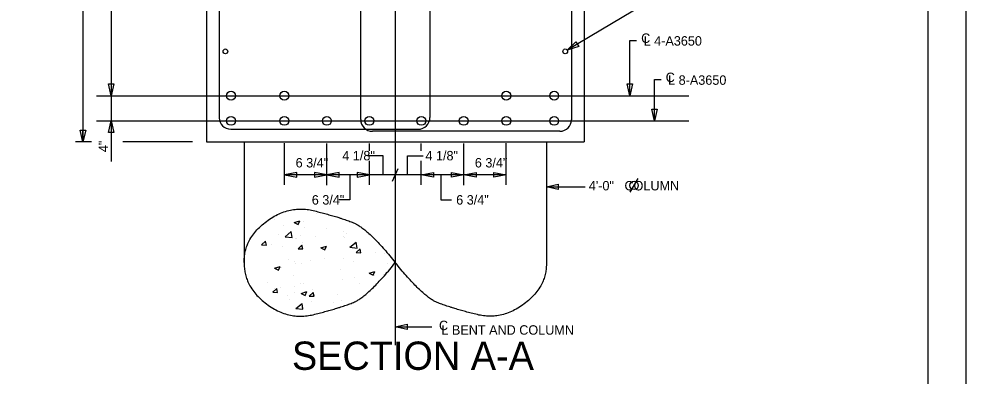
# Model space of a CAD drawing. Extents: x -133.1 to -97, y -1.7 to 20.3.
# Drawn here: x -109.68 to -97.14, y 7.51 to 12.24 of the extents above; entities that cross this region are included whole.
import ezdxf

# ---------------------------------------------------------------- set-up
doc = ezdxf.new("R2010")
doc.units = 0
for name, color, linetype in [('BR_AUTO DIMENSION', 7, 'Continuous'), ('BR_BORDER LINES', 7, 'Continuous'), ('BR_CENTER LINES', 7, 'Continuous'), ('BR_CONCRETE', 7, 'Continuous'), ('BR_REBAR', 7, 'Continuous'), ('BR_TEXT', 7, 'Continuous'), ('Level 31', 7, 'Continuous')]:
    doc.layers.add(name, color=color, linetype=linetype)

msp = doc.modelspace()

# ---------------------------------------------------------------- linework, layer by layer
at = {"layer": 'BR_AUTO DIMENSION'}
for p, q in [((-108.459, 15.581), (-108.459, 10.355)), ((-108.833, 15.366), (-108.834, 10.616)), ((-100.118, 13.205), (-102.422, 11.832)), ((-108.72, 10.616), (-108.931, 10.616)), ((-107.385, 10.616), (-108.304, 10.616)), ((-106.167, 10.047), (-106.167, 10.598)), ((-105.604, 10.041), (-105.604, 10.593)), ((-105.042, 10.495), (-105.042, 10.595)), ((-104.354, 10.495), (-104.354, 10.595)), ((-103.792, 10.041), (-103.792, 10.593)), ((-103.23, 10.047), (-103.23, 10.598)), ((-104.861, 10.433), (-105.067, 10.433)), ((-104.861, 10.179), (-104.861, 10.433)), ((-104.536, 10.179), (-104.536, 10.433)), ((-104.536, 10.433), (-104.329, 10.433)), ((-105.042, 10.047), (-105.042, 10.365)), ((-104.354, 10.047), (-104.354, 10.365)), ((-103.23, 10.179), (-106.167, 10.179)), ((-105.3, 10.179), (-105.3, 9.846)), ((-104.735, 10.096), (-104.661, 10.261)), ((-104.097, 10.179), (-104.097, 9.846)), ((-102.698, 10.021), (-102.186, 10.021)), ((-105.3, 9.846), (-105.444, 9.846)), ((-104.097, 9.846), (-103.953, 9.846)), ((-104.698, 8.167), (-104.215, 8.167))]:
    msp.add_line(p, q, dxfattribs=at)
for points in [[(-102.269, 11.881), (-102.422, 11.832), (-102.306, 11.943)], [(-108.423, 11.383), (-108.459, 11.227), (-108.495, 11.383)], [(-101.556, 11.383), (-101.592, 11.227), (-101.628, 11.383)], [(-101.231, 11.05), (-101.267, 10.894), (-101.303, 11.05)], [(-108.495, 10.738), (-108.459, 10.894), (-108.423, 10.738)], [(-108.798, 10.772), (-108.834, 10.616), (-108.87, 10.772)], [(-106.004, 10.21), (-106.167, 10.179), (-106.004, 10.147)], [(-105.767, 10.147), (-105.605, 10.179), (-105.767, 10.21)], [(-105.442, 10.21), (-105.605, 10.179), (-105.442, 10.147)], [(-105.205, 10.147), (-105.042, 10.179), (-105.205, 10.21)], [(-104.192, 10.147), (-104.354, 10.179), (-104.192, 10.21)], [(-103.954, 10.21), (-103.792, 10.179), (-103.954, 10.147)], [(-103.629, 10.147), (-103.792, 10.179), (-103.629, 10.21)], [(-103.392, 10.21), (-103.229, 10.179), (-103.392, 10.147)], [(-102.542, 9.985), (-102.698, 10.021), (-102.542, 10.057)], [(-104.542, 8.131), (-104.698, 8.167), (-104.542, 8.203)]]:
    msp.add_lwpolyline(points, close=True, dxfattribs=at)
for points in [[(-101.592, 11.227), (-101.592, 11.959), (-101.504, 11.959)], [(-101.267, 10.894), (-101.267, 11.44), (-101.18, 11.44)]]:
    msp.add_lwpolyline(points, dxfattribs=at)
at = {"layer": 'BR_BORDER LINES'}
msp.add_line((-97.642, -1.191), (-97.642, 19.809), dxfattribs=at)
at = {"layer": 'BR_CENTER LINES'}
for p, q in [((-104.698, 18.553), (-104.698, 7.924)), ((-108.656, 11.227), (-100.812, 11.227)), ((-108.656, 10.894), (-100.812, 10.894))]:
    msp.add_line(p, q, dxfattribs=at)
at = {"layer": 'BR_CONCRETE'}
for p, q in [((-107.198, 16.054), (-107.198, 10.616)), ((-102.198, 15.366), (-102.198, 10.616)), ((-107.198, 10.616), (-102.198, 10.616)), ((-106.698, 10.616), (-106.698, 8.985)), ((-102.698, 10.616), (-102.698, 8.984)), ((-105.742, 9.663), (-105.742, 9.663)), ((-106.3, 9.594), (-106.3, 9.594)), ((-106.038, 9.549), (-105.963, 9.572)), ((-106.038, 9.549), (-105.985, 9.521)), ((-105.985, 9.521), (-105.963, 9.572)), ((-105.918, 9.566), (-105.918, 9.566)), ((-106.173, 9.513), (-106.173, 9.513)), ((-106.158, 9.359), (-106.075, 9.427)), ((-106.063, 9.348), (-106.075, 9.427)), ((-105.898, 9.487), (-105.898, 9.487)), ((-105.611, 9.468), (-105.611, 9.468)), ((-105.378, 9.423), (-105.378, 9.423)), ((-106.468, 9.253), (-106.417, 9.301)), ((-106.404, 9.249), (-106.417, 9.301)), ((-106.244, 9.393), (-106.244, 9.393)), ((-106.158, 9.359), (-106.063, 9.348)), ((-106.023, 9.335), (-106.023, 9.335)), ((-106.003, 9.339), (-106.003, 9.339)), ((-105.957, 9.375), (-105.957, 9.375)), ((-105.931, 9.289), (-105.931, 9.289)), ((-105.755, 9.362), (-105.755, 9.362)), ((-105.385, 9.356), (-105.385, 9.356)), ((-105.375, 9.351), (-105.375, 9.351)), ((-105.349, 9.404), (-105.349, 9.404)), ((-105.3, 9.221), (-105.217, 9.289)), ((-105.205, 9.21), (-105.217, 9.289)), ((-106.468, 9.253), (-106.404, 9.249)), ((-106.414, 9.265), (-106.414, 9.265)), ((-106.342, 9.256), (-106.342, 9.256)), ((-106.187, 9.236), (-106.187, 9.236)), ((-105.986, 9.201), (-105.934, 9.249)), ((-105.986, 9.201), (-105.921, 9.197)), ((-105.921, 9.197), (-105.934, 9.249)), ((-105.684, 9.214), (-105.609, 9.236)), ((-105.684, 9.214), (-105.631, 9.186)), ((-105.631, 9.186), (-105.609, 9.236)), ((-105.3, 9.221), (-105.205, 9.21)), ((-105.217, 9.149), (-105.165, 9.197)), ((-105.153, 9.144), (-105.165, 9.196)), ((-106.111, 9.063), (-106.111, 9.063)), ((-106.037, 9.033), (-106.037, 9.033)), ((-105.825, 9.044), (-105.825, 9.044)), ((-105.631, 9.075), (-105.631, 9.075)), ((-105.388, 9.074), (-105.388, 9.074)), ((-105.217, 9.149), (-105.153, 9.144)), ((-104.955, 9.144), (-104.955, 9.144)), ((-104.837, 9.133), (-104.837, 9.133)), ((-106.299, 8.945), (-106.224, 8.967)), ((-106.299, 8.945), (-106.246, 8.917)), ((-106.246, 8.917), (-106.224, 8.967)), ((-106.2, 8.958), (-106.2, 8.958)), ((-106.02, 9.006), (-106.02, 9.006)), ((-105.944, 9.011), (-105.944, 9.011)), ((-105.422, 8.925), (-105.422, 8.925)), ((-105.253, 9.025), (-105.253, 9.025)), ((-104.797, 9.009), (-104.797, 9.009)), ((-106.047, 8.842), (-106.047, 8.842)), ((-105.401, 8.796), (-105.401, 8.796)), ((-105.236, 8.815), (-105.236, 8.815)), ((-105.045, 8.878), (-104.97, 8.901)), ((-105.045, 8.878), (-104.991, 8.85)), ((-104.991, 8.85), (-104.97, 8.9)), ((-104.968, 8.843), (-104.968, 8.843)), ((-104.85, 8.855), (-104.85, 8.855)), ((-106.386, 8.759), (-106.386, 8.759)), ((-106.32, 8.626), (-106.268, 8.674)), ((-106.301, 8.677), (-106.301, 8.677)), ((-106.256, 8.622), (-106.268, 8.674)), ((-106.213, 8.681), (-106.213, 8.681)), ((-106.033, 8.705), (-106.033, 8.705)), ((-105.957, 8.734), (-105.957, 8.734)), ((-105.913, 8.746), (-105.913, 8.746)), ((-105.79, 8.659), (-105.79, 8.659)), ((-105.166, 8.743), (-105.166, 8.743)), ((-106.32, 8.626), (-106.256, 8.622)), ((-106.319, 8.637), (-106.319, 8.637)), ((-106.13, 8.576), (-106.13, 8.576)), ((-106.033, 8.618), (-106.033, 8.618)), ((-105.945, 8.609), (-105.87, 8.632)), ((-105.945, 8.609), (-105.892, 8.581)), ((-105.892, 8.581), (-105.87, 8.632)), ((-105.837, 8.574), (-105.785, 8.622)), ((-105.837, 8.574), (-105.773, 8.57)), ((-105.773, 8.57), (-105.785, 8.622)), ((-105.461, 8.6), (-105.461, 8.6)), ((-106.094, 8.525), (-106.094, 8.525)), ((-106.016, 8.41), (-105.933, 8.477)), ((-106.016, 8.41), (-105.921, 8.398)), ((-105.97, 8.457), (-105.97, 8.457)), ((-105.921, 8.398), (-105.933, 8.477)), ((-105.909, 8.417), (-105.909, 8.417)), ((-105.807, 8.506), (-105.807, 8.506)), ((-105.518, 8.487), (-105.518, 8.487)), ((-105.414, 8.519), (-105.414, 8.519))]:
    msp.add_line(p, q, dxfattribs=at)
for points in [[(-106.698, 9.017), (-106.708, 9.333), (-106.109, 9.786), (-105.449, 9.623), (-105.06, 9.468), (-104.698, 9.017)], [(-106.698, 9.017), (-106.708, 8.7), (-106.109, 8.247), (-105.449, 8.41), (-105.06, 8.566), (-104.698, 9.017)], [(-102.698, 9.017), (-102.688, 8.7), (-103.288, 8.247), (-103.948, 8.41), (-104.337, 8.566), (-104.698, 9.017)]]:
    msp.add_open_spline(points, degree=2, dxfattribs=at)
at = {"layer": 'BR_REBAR'}
for p, q in [((-105.157, 15.098), (-105.157, 10.912)), ((-102.365, 15.096), (-102.365, 10.91)), ((-107.032, 15.046), (-107.032, 10.937)), ((-104.24, 15.044), (-104.24, 10.939)), ((-106.878, 10.783), (-104.396, 10.783)), ((-102.519, 10.756), (-105, 10.756))]:
    msp.add_line(p, q, dxfattribs=at)
for centre, radius in [((-106.948, 11.815), 0.0313), ((-102.448, 11.815), 0.0313), ((-106.873, 11.227), 0.0588), ((-106.167, 11.227), 0.0588), ((-103.229, 11.227), 0.0588), ((-102.594, 11.227), 0.0588), ((-106.873, 10.894), 0.0588), ((-106.167, 10.894), 0.0588), ((-105.604, 10.894), 0.0588), ((-105.042, 10.894), 0.0588), ((-104.354, 10.894), 0.0588), ((-103.792, 10.894), 0.0588), ((-103.229, 10.894), 0.0588), ((-102.594, 10.894), 0.0588)]:
    msp.add_circle(centre, radius, dxfattribs=at)
for centre, start, end in [((-106.875, 10.939), 181.025, 268.975), ((-105, 10.912), 180, 270), ((-104.396, 10.939), 270, 0), ((-102.521, 10.912), 271.025, 358.975)]:
    msp.add_arc(centre, 0.156, start, end, dxfattribs=at)
at = {"layer": 'BR_TEXT'}
for p, q in [((-108.834, 10.616), (-108.834, 10.764)), ((-101.589, 9.948), (-101.484, 10.13))]:
    msp.add_line(p, q, dxfattribs=at)
msp.add_circle((-101.536, 10.039), 0.055, dxfattribs=at)
at = {"layer": 'Level 31'}
msp.add_lwpolyline([(-133.141, -1.691), (-97.141, -1.691), (-97.141, 20.309), (-133.141, 20.309)], close=True, dxfattribs=at)

# ---------------------------------------------------------------- texts
at = {"layer": 'BR_TEXT'}
for s, rotation, p in [('C', 360, (-101.443, 11.927)), ('L 4-A3650', 360, (-101.41, 11.891)), ('C', 360, (-101.118, 11.408)), ('L 8-A3650', 360, (-101.086, 11.372)), ('4"', 90, (-108.501, 10.48)), ('6 3/4"', 360, (-106.018, 10.277)), ('6 3/4"', 360, (-103.645, 10.277)), ('4\'-0"   COLUMN', 360, (-102.136, 9.973)), ('6 3/4"', 360, (-105.804, 9.785)), ('6 3/4"', 360, (-103.892, 9.785)), ('C', 360, (-104.12, 8.122)), ('L BENT AND COLUMN', 360, (-104.088, 8.062))]:
    msp.add_text(s, height=0.125, rotation=rotation, dxfattribs=at).set_placement(p)
for s, height, p in [('4 1/8"', 0.125, (-105.4, 10.371)), ('4 1/8"', 0.125, (-104.299, 10.371)), ('SECTION A-A', 0.375, (-106.067, 7.596))]:
    msp.add_text(s, height=height, dxfattribs=at).set_placement(p)

doc.saveas('drawing.dxf')
